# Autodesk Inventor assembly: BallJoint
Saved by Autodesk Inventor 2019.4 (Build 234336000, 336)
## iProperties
Created: 2020-04
Part Number: BallJoint
Document SubType Name: Assembly
Designer: Administrator
Title: BallJoint v14
Author: Administrator
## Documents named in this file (3)
- c:\worker\convert-fusion-r03\tmp\job-1\48\output\files\ccae6ef3-9f0e-42ff-b199-3a2c6474057a\BallJoint v14_4.iam
- c:\worker\convert-fusion-r03\tmp\job-1\48\output\files\ccae6ef3-9f0e-42ff-b199-3a2c6474057a\Component1_1.ipt
- c:\worker\convert-fusion-r03\tmp\job-1\48\output\files\ccae6ef3-9f0e-42ff-b199-3a2c6474057a\Component2_1.ipt
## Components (2 placed, 2 different names)
1. Component1:1
2. Component2:1
